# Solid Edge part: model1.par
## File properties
Author: Vicky Raina
Template: normal.par
Last saved by: CADCIM
Revision: 6
Application: Solid Edge
Accuracy: 0.99
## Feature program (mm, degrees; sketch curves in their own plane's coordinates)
sketch for "unnamed Protrusion 1" plane through (0, 0, 0) normal (0, -1, 0) x-axis (1, 0, 0)
  arc centre (60, 0) radius 30 from (60, 30) to (60, -30) cw
  line (104, -30) -> (60, -30)
  line (104, 18) -> (104, -30)
  line (164, 18) -> (104, 18)
  line (164, -4) -> (164, 18)
  line (182, -4) -> (164, -4)
  line (182, -4) -> (182, 36)
  line (142, 36) -> (182, 36)
  line (142, 30) -> (142, 36)
  line (60, 30) -> (142, 30)
extrude "unnamed Protrusion 1" add finite 54 symmetric
sketch for "ExtrudedProtrusion_6" #1 plane through (0, 0, 0) normal (0, -1, 0) x-axis (1, 0, 0)
  arc centre (60, 0) radius 30 from (60, 30) to (60, -30) ccw
  arc centre (60, 0) radius 30 from (60, 30) to (60, -30) cw
sketch for "ExtrudedProtrusion_6" #2 plane through (0, 0, 0) normal (0, -1, 0) x-axis (1, 0, 0)
  circle centre (60, 0) radius 18
extrude "ExtrudedProtrusion_6" add finite 66 symmetric
sketch for "ExtrudedProtrusion_7" plane through (0, 0, 0) normal (0, -1, 0) x-axis (1, 0, 0)
  line (104, -30) -> (164, -4)
  line (164, -4) -> (164, 18)
  line (164, 18) -> (104, 18)
  line (104, 18) -> (104, -30)
extrude "ExtrudedProtrusion_7" add finite 18 symmetric
sketch for "ExtrudedProtrusion_8" plane through (0, 0, 0) normal (0, -1, 0) x-axis (1, 0, 0)
  line (200, 76) -> (200, -4)
  line (200, -4) -> (182, -4)
  line (182, -4) -> (182, 36)
  line (182, 76) -> (182, 36)
  line (182, 76) -> (200, 76)
extrude "ExtrudedProtrusion_8" add finite 92 symmetric
sketch for "ExtrudedProtrusion_9" plane through (0, 0, 0) normal (0, -1, 0) x-axis (1, 0, 0)
  line (142, 36) -> (182, 76)
  line (182, 76) -> (182, 36)
  line (142, 36) -> (182, 36)
extrude "ExtrudedProtrusion_9" add finite 12 symmetric
sketch for "unnamed Hole 1" plane through (200, 0, 36) normal (1, 0, 0) x-axis (0, 1, 0)
hole "unnamed Hole 1" through
sketch for "Hole_1" plane through (200, 0, 36) normal (1, 0, 0) x-axis (0, 1, 0)
  hole centre (-30, 22) bore radius 8
hole "Hole_1" diameter 16 through
pattern "unnamed Pattern 1" of "unnamed Hole 1", "Hole_1"
fillet "unnamed Round 1"
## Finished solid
Body 1: solid body, 34 faces, 81 edges, 46 vertices.
  Faces by surface: plane 28, cylinder 6
  Edges by curve: line 67, circle 14
Bounding box of the edges (mm): 170.000 x 92.000 x 106.000, from (30, -46, -30) to (200, 46, 76).
Cylindrical faces by radius (mm): R8 x2, R16 x2, R18 x1, R30 x1
Planar faces by outward normal: +x 3, +y 5, +z 4, -x 5, -y 5, -z 4, oblique 2
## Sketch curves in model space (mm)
circle centre (60, 0, 0) radius 18
line (182, 0, -4) -> (164, 0, -4)
line (104, 0, -30) -> (60, 0, -30)
arc centre (60, 0, 0) radius 30 from (60, 0, 30) through (30.0132, 0, -0.889) to (60, 0, -30)
arc centre (60, 0, 0) radius 30 from (60, 0, 30) through (89.9868, 0, -0.889) to (60, 0, -30)
line (142, 0, 36) -> (182, 0, 76)
line (142, 0, 36) -> (182, 0, 36)
line (104, 0, -30) -> (164, 0, -4)
line (182, 0, 76) -> (182, 0, 36)
line (182, 0, -4) -> (182, 0, 36)
line (142, 0, 30) -> (142, 0, 36)
line (60, 0, 30) -> (142, 0, 30)
line (104, 0, 18) -> (104, 0, -30)
line (164, 0, 18) -> (104, 0, 18)
line (164, 0, -4) -> (164, 0, 18)
line (200, 0, -4) -> (182, 0, -4)
line (200, 0, 76) -> (200, 0, -4)
line (182, 0, 76) -> (200, 0, 76)
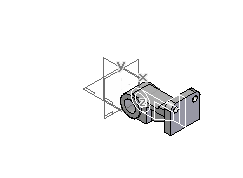
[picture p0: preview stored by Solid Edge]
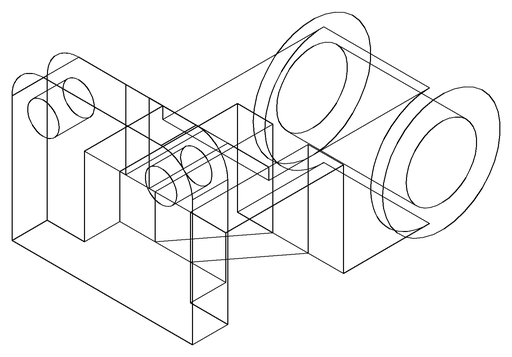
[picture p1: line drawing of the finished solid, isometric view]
